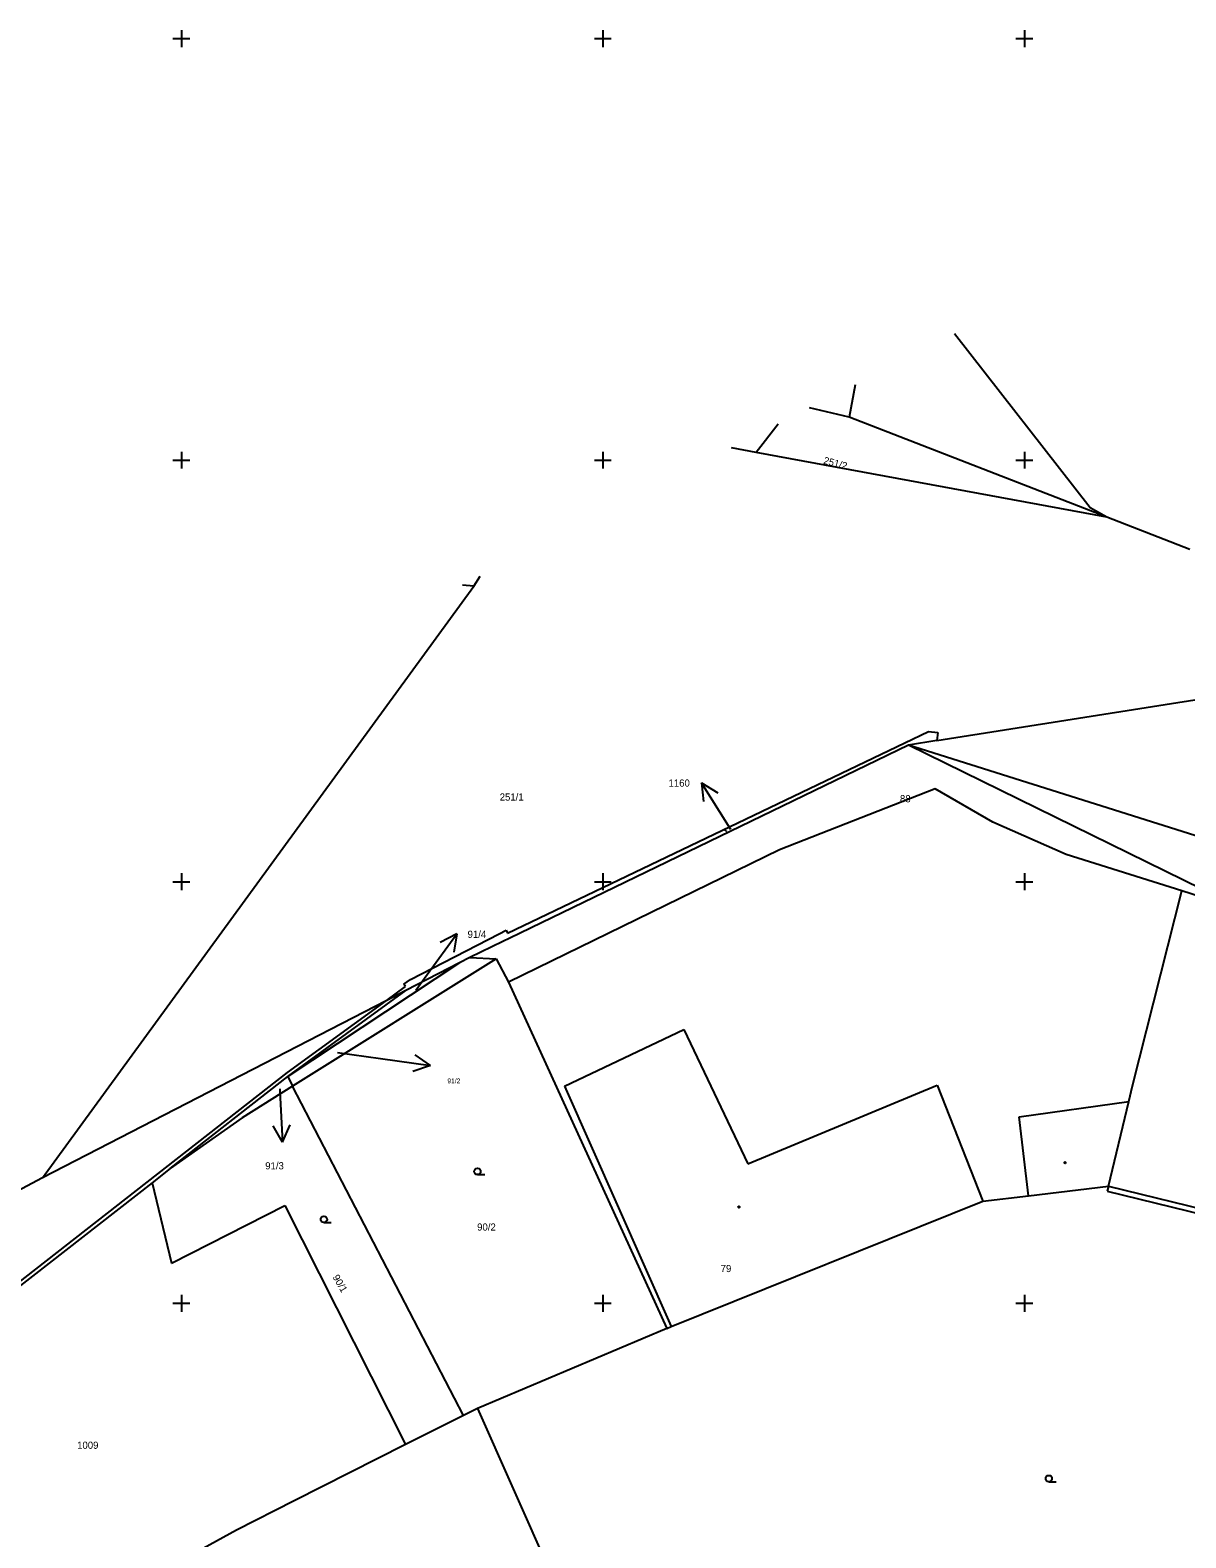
# Model space of a CAD drawing. Extents: x -711081 to -709338, y -1025122 to -1024092.
# Drawn here: x -710884 to -710815.4, y -1024888.9 to -1024799.5 of the extents above; entities that cross this region are included whole.
import ezdxf

# ---------------------------------------------------------------- set-up
doc = ezdxf.new("R2010")
doc.units = 0
for name, color, linetype in [('Z_hektometricka_sit', 7, 'Continuous'), ('Z_katastr_cisla_pozemkova', 7, 'Continuous'), ('Z_katastr_cisla_stavebni', 7, 'Continuous'), ('Z_katastr_hranice', 7, 'Continuous'), ('Z_katastr_hranice_katastralniho_uzemi', 7, 'Continuous'), ('Z_katastr_parcelni_cislo_odkaz', 7, 'Continuous'), ('Z_katastr_vnitrni_kresba', 7, 'Continuous'), ('Z_katastr_znacky_budov', 7, 'Continuous'), ('Z_katastr_znacky_kultur', 7, 'Continuous')]:
    doc.layers.add(name, color=color, linetype=linetype)

msp = doc.modelspace()

# ---------------------------------------------------------------- linework, layer by layer
at = {"layer": 'Z_hektometricka_sit'}
for p, q in [((-710875, -1024799.5), (-710875, -1024800.5)), ((-710850, -1024799.5), (-710850, -1024800.5)), ((-710825, -1024799.5), (-710825, -1024800.5)), ((-710875.5, -1024800), (-710874.5, -1024800)), ((-710850.5, -1024800), (-710849.5, -1024800)), ((-710825.5, -1024800), (-710824.5, -1024800)), ((-710875, -1024824.5), (-710875, -1024825.5)), ((-710850, -1024824.5), (-710850, -1024825.5)), ((-710825, -1024824.5), (-710825, -1024825.5)), ((-710875.5, -1024825), (-710874.5, -1024825)), ((-710850.5, -1024825), (-710849.5, -1024825)), ((-710825.5, -1024825), (-710824.5, -1024825)), ((-710875, -1024849.5), (-710875, -1024850.5)), ((-710850, -1024849.5), (-710850, -1024850.5)), ((-710825, -1024849.5), (-710825, -1024850.5)), ((-710875.5, -1024850), (-710874.5, -1024850)), ((-710850.5, -1024850), (-710849.5, -1024850)), ((-710825.5, -1024850), (-710824.5, -1024850)), ((-710875, -1024874.5), (-710875, -1024875.5)), ((-710850, -1024874.5), (-710850, -1024875.5)), ((-710825, -1024874.5), (-710825, -1024875.5)), ((-710875.5, -1024875), (-710874.5, -1024875)), ((-710850.5, -1024875), (-710849.5, -1024875)), ((-710825.5, -1024875), (-710824.5, -1024875))]:
    msp.add_line(p, q, dxfattribs=at)
at = {"layer": 'Z_katastr_hranice'}
for p, q in [((-710821.09, -1024827.82), (-710829.135, -1024817.518)), ((-710835.04, -1024820.531), (-710835.4, -1024822.45)), ((-710835.4, -1024822.45), (-710837.734, -1024821.905)), ((-710820.11, -1024828.38), (-710835.4, -1024822.45)), ((-710839.61, -1024822.863), (-710840.9, -1024824.54)), ((-710840.9, -1024824.54), (-710842.365, -1024824.268)), ((-710820.11, -1024828.38), (-710840.9, -1024824.54)), ((-710820.11, -1024828.38), (-710821.09, -1024827.82)), ((-710815.19, -1024830.29), (-710820.11, -1024828.38)), ((-710883.24, -1024867.57), (-710857.65, -1024832.48)), ((-710857.65, -1024832.48), (-710858.332, -1024832.415)), ((-710857.65, -1024832.48), (-710857.282, -1024831.88)), ((-710830.2, -1024841.63), (-710807.29, -1024838.02)), ((-710832.08, -1024841.76), (-710830.69, -1024841.09)), ((-710830.69, -1024841.09), (-710830.14, -1024841.16)), ((-710830.14, -1024841.16), (-710830.2, -1024841.63)), ((-710855.66, -1024853.05), (-710832.08, -1024841.76)), ((-710830.2, -1024841.63), (-710831.88, -1024841.9)), ((-710811.54, -1024851.88), (-710831.88, -1024841.9)), ((-710830.28, -1024844.5), (-710839.53, -1024848.11)), ((-710826.87, -1024846.47), (-710830.28, -1024844.5)), ((-710822.52, -1024848.39), (-710826.87, -1024846.47)), ((-710839.53, -1024848.11), (-710855.59, -1024855.95)), ((-710815.65, -1024850.54), (-710822.52, -1024848.39)), ((-710818.59, -1024862.11), (-710815.65, -1024850.54)), ((-710811.54, -1024851.88), (-710815.65, -1024850.54)), ((-710861.41, -1024855.8), (-710856.16, -1024853.09)), ((-710856.16, -1024853.09), (-710855.74, -1024852.88)), ((-710855.74, -1024852.88), (-710855.66, -1024853.05)), ((-710858.51, -1024854.82), (-710868.69, -1024861.56)), ((-710856.32, -1024854.57), (-710868.4, -1024862.13)), ((-710857.89, -1024854.5), (-710856.32, -1024854.57)), ((-710856.32, -1024854.57), (-710855.59, -1024855.95)), ((-710861.81, -1024856.07), (-710861.41, -1024855.8)), ((-710868.69, -1024861.56), (-710861.68, -1024856.45)), ((-710862.86, -1024857.06), (-710861.7, -1024856.22)), ((-710861.7, -1024856.22), (-710861.81, -1024856.07)), ((-710855.59, -1024855.95), (-710846.21, -1024876.5)), ((-710868.71, -1024861.31), (-710862.86, -1024857.06)), ((-710895.88, -1024882.53), (-710868.71, -1024861.31)), ((-710875.66, -1024867.01), (-710868.69, -1024861.56)), ((-710868.69, -1024861.56), (-710868.4, -1024862.13)), ((-710818.81, -1024863.04), (-710818.59, -1024862.11)), ((-710868.4, -1024862.13), (-710871.4, -1024864.01)), ((-710858.27, -1024881.65), (-710868.4, -1024862.13)), ((-710820.01, -1024868.06), (-710818.81, -1024863.04)), ((-710871.4, -1024864.01), (-710875.66, -1024867.01)), ((-710875.66, -1024867.01), (-710876.74, -1024867.85)), ((-710876.74, -1024867.85), (-710886.18, -1024875.21)), ((-710876.74, -1024867.85), (-710875.58, -1024872.63)), ((-710824.76, -1024868.63), (-710820.01, -1024868.06)), ((-710820.01, -1024868.06), (-710820.08, -1024868.35)), ((-710820.08, -1024868.35), (-710804.81, -1024872.08)), ((-710875.58, -1024872.63), (-710868.86, -1024869.2)), ((-710868.86, -1024869.2), (-710861.71, -1024883.38)), ((-710845.94, -1024876.38), (-710827.46, -1024868.95)), ((-710827.46, -1024868.95), (-710824.76, -1024868.63)), ((-710846.21, -1024876.5), (-710845.94, -1024876.38)), ((-710846.21, -1024876.5), (-710857.43, -1024881.23)), ((-710858.27, -1024881.65), (-710861.71, -1024883.38)), ((-710857.43, -1024881.23), (-710858.27, -1024881.65)), ((-710857.43, -1024881.23), (-710852.58, -1024892.17)), ((-710861.71, -1024883.38), (-710868.31, -1024886.72)), ((-710868.31, -1024886.72), (-710871.74, -1024888.45)), ((-710871.74, -1024888.45), (-710887.05, -1024896.87))]:
    msp.add_line(p, q, dxfattribs=at)
at = {"layer": 'Z_katastr_hranice_katastralniho_uzemi'}
for p, q in [((-710831.88, -1024841.9), (-710855.52, -1024853.35)), ((-710831.88, -1024841.9), (-710855.52, -1024853.35)), ((-710811.2, -1024848.42), (-710831.88, -1024841.9)), ((-710811.2, -1024848.42), (-710831.88, -1024841.9)), ((-710855.94, -1024853.55), (-710857.89, -1024854.5)), ((-710855.94, -1024853.55), (-710857.89, -1024854.5)), ((-710855.52, -1024853.35), (-710855.94, -1024853.55)), ((-710855.52, -1024853.35), (-710855.94, -1024853.55)), ((-710858.51, -1024854.82), (-710861.68, -1024856.45)), ((-710858.51, -1024854.82), (-710861.68, -1024856.45)), ((-710857.89, -1024854.5), (-710858.51, -1024854.82)), ((-710857.89, -1024854.5), (-710858.51, -1024854.82)), ((-710861.68, -1024856.45), (-710862.86, -1024857.06)), ((-710861.68, -1024856.45), (-710862.86, -1024857.06)), ((-710862.86, -1024857.06), (-710883.24, -1024867.57)), ((-710862.86, -1024857.06), (-710883.24, -1024867.57)), ((-710883.24, -1024867.57), (-710901.34, -1024877.12)), ((-710883.24, -1024867.57), (-710901.34, -1024877.12))]:
    msp.add_line(p, q, dxfattribs=at)
at = {"layer": 'Z_katastr_parcelni_cislo_odkaz'}
for p, q in [((-710842.55, -1024846.68), (-710844.14, -1024844.135)), ((-710844.14, -1024844.135), (-710843.185, -1024844.719)), ((-710844.14, -1024844.135), (-710844.034, -1024845.25)), ((-710842.41, -1024846.9), (-710842.55, -1024846.68)), ((-710860.42, -1024855.51), (-710858.656, -1024853.082)), ((-710858.656, -1024853.082), (-710859.65, -1024853.598)), ((-710858.656, -1024853.082), (-710858.84, -1024854.187)), ((-710861.1, -1024856.43), (-710860.42, -1024855.51)), ((-710865.74, -1024860.12), (-710863.19, -1024860.48)), ((-710860.218, -1024860.898), (-710861.14, -1024860.262)), ((-710863.19, -1024860.48), (-710860.218, -1024860.898)), ((-710860.218, -1024860.898), (-710861.28, -1024861.254)), ((-710869.17, -1024862.28), (-710869.16, -1024862.45)), ((-710869.16, -1024862.45), (-710869.003, -1024865.447)), ((-710869.003, -1024865.447), (-710869.555, -1024864.473)), ((-710869.003, -1024865.447), (-710868.555, -1024864.421))]:
    msp.add_line(p, q, dxfattribs=at)
at = {"layer": 'Z_katastr_vnitrni_kresba'}
for p, q in [((-710852.27, -1024862.13), (-710845.19, -1024858.77)), ((-710845.19, -1024858.77), (-710841.41, -1024866.73)), ((-710841.41, -1024866.73), (-710830.18, -1024862.07)), ((-710830.18, -1024862.07), (-710827.46, -1024868.95)), ((-710852.27, -1024862.13), (-710845.94, -1024876.38)), ((-710825.31, -1024863.94), (-710818.81, -1024863.04)), ((-710824.76, -1024868.63), (-710825.31, -1024863.94)), ((-710820.01, -1024868.06), (-710804.74, -1024871.79))]:
    msp.add_line(p, q, dxfattribs=at)
at = {"layer": 'Z_katastr_znacky_budov'}
msp.add_line((-710842.705, -1024846.974), (-710842.695, -1024846.986), dxfattribs=at)
for centre in [(-710822.582, -1024866.66), (-710841.932, -1024869.29)]:
    msp.add_circle(centre, 0.0437, dxfattribs=at)
for centre, start, end in [((-710842.722, -1024846.983), 29.29136, 181.21887), ((-710842.678, -1024846.977), 209.29136, 1.21887)]:
    msp.add_arc(centre, 0.0191, start, end, dxfattribs=at)
at = {"layer": 'Z_katastr_znacky_kultur'}
for p, q in [((-710857.438, -1024867.37), (-710857.001, -1024867.37)), ((-710866.548, -1024870.21), (-710866.111, -1024870.21)), ((-710823.548, -1024885.58), (-710823.111, -1024885.58))]:
    msp.add_line(p, q, dxfattribs=at)
for centre in [(-710857.438, -1024867.182), (-710866.548, -1024870.022), (-710823.548, -1024885.392)]:
    msp.add_circle(centre, 0.187, dxfattribs=at)

# ---------------------------------------------------------------- texts
at = {"layer": 'Z_katastr_cisla_pozemkova'}
for s, rotation, p in [('251/2', 345, (-710836.949, -1024825.201)), ('90/1', 300, (-710866.048, -1024873.448))]:
    msp.add_text(s, height=0.425, rotation=rotation, dxfattribs=at).set_placement(p)
for s, height, p in [('251/1', 0.425, (-710856.12, -1024845.19)), ('88', 0.425, (-710832.378, -1024845.289)), ('91/4', 0.425, (-710858.024, -1024853.33)), ('91/2', 0.285, (-710859.22, -1024861.954)), ('91/3', 0.425, (-710870.029, -1024867.059)), ('90/2', 0.425, (-710857.458, -1024870.69)), ('1009', 0.425, (-710881.185, -1024883.63))]:
    msp.add_text(s, height=height, dxfattribs=at).set_placement(p)
at = {"layer": 'Z_katastr_cisla_stavebni'}
for s, p in [('1160', (-710846.106, -1024844.36)), ('79', (-710843.013, -1024873.15))]:
    msp.add_text(s, height=0.425, dxfattribs=at).set_placement(p)

doc.saveas('drawing.dxf')
